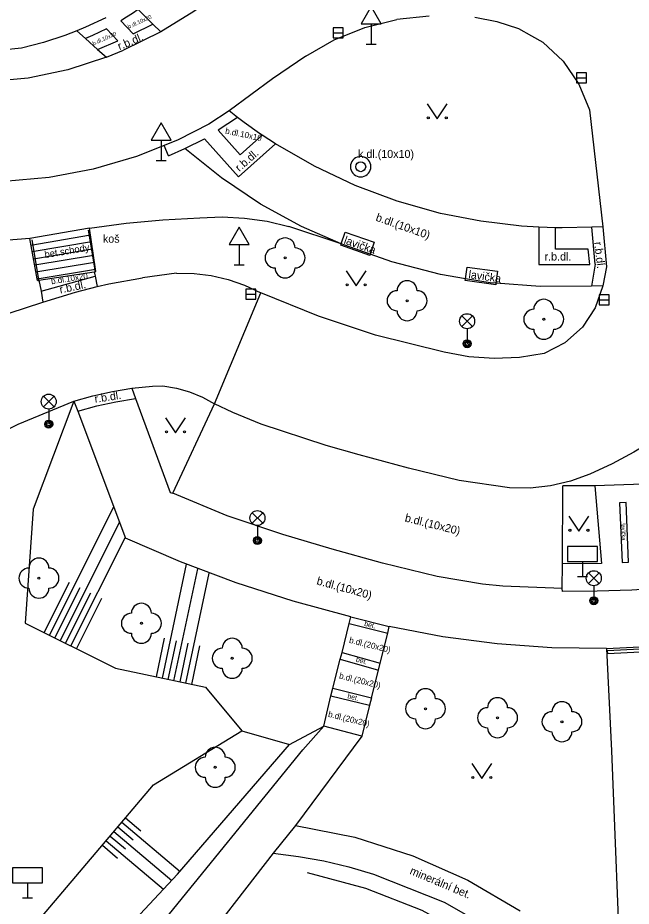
# Model space of a CAD drawing. Extents: x -600309 to -598967, y -1161267 to -1160292.
# Drawn here: x -599798.91 to -599768.25, y -1160664.5 to -1160620.07 of the extents above; entities that cross this region are included whole.
import ezdxf

# ---------------------------------------------------------------- set-up
doc = ezdxf.new("R2010")
doc.units = 0
for name, color, linetype in [('Level 10', 7, 'Continuous'), ('Level 11', 7, 'Continuous'), ('Level 14', 7, 'Continuous'), ('Level 15', 7, 'Continuous'), ('Level 20', 7, 'Continuous'), ('Level 22', 7, 'Continuous'), ('Level 24', 7, 'Continuous'), ('Level 27', 7, 'Continuous'), ('Level 28', 7, 'Continuous'), ('Level 33', 7, 'Continuous'), ('Level 34', 7, 'Continuous'), ('Level 36', 7, 'Continuous'), ('Level 40', 7, 'Continuous'), ('Level 42', 7, 'Continuous'), ('Level 53', 7, 'Continuous'), ('Level 9', 7, 'Continuous')]:
    doc.layers.add(name, color=color, linetype=linetype)

msp = doc.modelspace()

# ---------------------------------------------------------------- linework, layer by layer
at = {"layer": 'Level 10'}
for points in [[(-599784.44, -1160615.96), (-599787.36, -1160617.84), (-599790.11, -1160619.76), (-599791.76, -1160620.78), (-599793.63, -1160621.69)], [(-599794.5, -1160620.07), (-599795.52, -1160620.55), (-599795.96, -1160620.73), (-599796.56, -1160620.96), (-599797.63, -1160621.31), (-599798.72, -1160621.59)], [(-599784.51, -1160621.99), (-599783.09, -1160621.17), (-599781.57, -1160620.56), (-599779.97, -1160620.16)], [(-599778.34, -1160619.99), (-599779.97, -1160620.16)], [(-599776.07, -1160620.04), (-599774.96, -1160620.26), (-599773.88, -1160620.61)], [(-599773.88, -1160620.61), (-599773.23, -1160620.98), (-599772.67, -1160621.3), (-599771.65, -1160622.25), (-599770.86, -1160623.39), (-599770.34, -1160624.68)], [(-599798.72, -1160621.59), (-599801.69, -1160621.89), (-599808.68, -1160621.69), (-599814.39, -1160621.56)], [(-599794.48, -1160622.05), (-599793.63, -1160621.69)], [(-599784.51, -1160621.99), (-599786.17, -1160623.13), (-599788.34, -1160624.73), (-599789.36, -1160625.4)], [(-599794.48, -1160622.05), (-599796.4, -1160622.68), (-599798.39, -1160623.09), (-599800.4, -1160623.28), (-599802.43, -1160623.24)], [(-599770.34, -1160624.68), (-599769.66, -1160630.52), (-599769.48, -1160632.52), (-599769.66, -1160633.48)], [(-599789.36, -1160625.4), (-599790.9, -1160626.18)], [(-599790.9, -1160626.18), (-599791.59, -1160626.46), (-599792.98, -1160627.01), (-599795.14, -1160627.64), (-599797.34, -1160628.06), (-599799.58, -1160628.26)], [(-599797.66, -1160634.29), (-599796.02, -1160633.79), (-599794.94, -1160633.51), (-599794.36, -1160633.38), (-599792.67, -1160633.07)], [(-599790.97, -1160632.85), (-599792.67, -1160633.07)], [(-599790.97, -1160632.85), (-599790.1, -1160632.86)], [(-599790.1, -1160632.86), (-599789.24, -1160632.96)], [(-599789.24, -1160632.96), (-599788.4, -1160633.16), (-599787.58, -1160633.45)], [(-599787.58, -1160633.45), (-599786.76, -1160633.83)], [(-599769.66, -1160633.48), (-599770.05, -1160634.58), (-599770.69, -1160635.55), (-599771.56, -1160636.33), (-599772.6, -1160636.86)], [(-599777.6, -1160636.79), (-599781.03, -1160635.95), (-599783.87, -1160634.99), (-599786.76, -1160633.83)], [(-599804.11, -1160637.13), (-599802.57, -1160636.26), (-599800.98, -1160635.5), (-599799.34, -1160634.84), (-599797.66, -1160634.29)], [(-599772.6, -1160636.86), (-599773.84, -1160637.06), (-599775.1, -1160637.11), (-599776.36, -1160637.02), (-599777.6, -1160636.79)], [(-599793.21, -1160638.6), (-599792.69, -1160638.54), (-599792.17, -1160638.5), (-599791.65, -1160638.47)], [(-599791.65, -1160638.47), (-599790.97, -1160638.59), (-599790.32, -1160638.78), (-599789.68, -1160639.04), (-599789.08, -1160639.37)], [(-599796.1, -1160639.24), (-599795.15, -1160638.97), (-599794.18, -1160638.76), (-599793.21, -1160638.6)], [(-599806.53, -1160645.11), (-599804.11, -1160643.33), (-599801.55, -1160641.75), (-599798.88, -1160640.39), (-599796.1, -1160639.24)], [(-599771.7, -1160648.61), (-599774.66, -1160648.49), (-599775.69, -1160648.4), (-599777.94, -1160648.01), (-599780.68, -1160647.34), (-599783.19, -1160646.65), (-599785.66, -1160645.91), (-599788.44, -1160644.97), (-599791.16, -1160643.84), (-599789.08, -1160639.37)], [(-599762.26, -1160642.58), (-599764.7, -1160643.07), (-599767.65, -1160643.39), (-599770.07, -1160643.48), (-599771.67, -1160643.48)], [(-599771.7, -1160648.61), (-599771.68, -1160647.37), (-599771.67, -1160643.48)]]:
    msp.add_lwpolyline(points, dxfattribs=at)
at = {"layer": 'Level 11'}
for points in [[(-599793.26, -1160619.29), (-599792.89, -1160619.66), (-599792.15, -1160620.39), (-599791.76, -1160620.78)], [(-599792.89, -1160619.66), (-599793.18, -1160619.86), (-599793.47, -1160620.05), (-599793.76, -1160620.23)], [(-599793.76, -1160620.23), (-599793.14, -1160620.87)], [(-599794.47, -1160620.63), (-599794.82, -1160620.8), (-599795.18, -1160620.96), (-599795.53, -1160621.11)], [(-599794.47, -1160620.63), (-599793.91, -1160621.23)], [(-599793.14, -1160620.87), (-599792.15, -1160620.39)], [(-599795.96, -1160620.73), (-599795.53, -1160621.11), (-599794.92, -1160621.66), (-599794.48, -1160622.05)], [(-599794.92, -1160621.66), (-599793.91, -1160621.23)], [(-599787.92, -1160625.06), (-599788.89, -1160625.7)], [(-599786.03, -1160626.38), (-599786.7, -1160625.95), (-599786.82, -1160625.86), (-599787.59, -1160625.31), (-599787.92, -1160625.06), (-599788.34, -1160624.73)], [(-599787.79, -1160626.92), (-599788.89, -1160625.7)], [(-599787.79, -1160626.92), (-599786.7, -1160625.95)], [(-599791.37, -1160626.98), (-599791.59, -1160626.46)], [(-599790.56, -1160626.61), (-599789.58, -1160626.13)], [(-599786.03, -1160626.38), (-599787.87, -1160628.02), (-599789.58, -1160626.13)], [(-599779.94, -1160629.24), (-599782.05, -1160628.46), (-599784.08, -1160627.5), (-599786.03, -1160626.38)], [(-599791.37, -1160626.98), (-599790.56, -1160626.61)], [(-599782.74, -1160631.38), (-599784.72, -1160630.51), (-599786.78, -1160629.39), (-599788.73, -1160628.08), (-599790.56, -1160626.61)], [(-599781.2601, -1160627.52), (-599781.2678, -1160627.4315), (-599781.2909, -1160627.3456), (-599781.3284, -1160627.265), (-599781.3794, -1160627.1922), (-599781.4422, -1160627.1294), (-599781.515, -1160627.0784), (-599781.5956, -1160627.0409), (-599781.6815, -1160627.0178), (-599781.77, -1160627.0101), (-599781.8585, -1160627.0178), (-599781.9444, -1160627.0409), (-599782.0249, -1160627.0784), (-599782.0978, -1160627.1294), (-599782.1606, -1160627.1922), (-599782.2116, -1160627.265), (-599782.2491, -1160627.3456), (-599782.2722, -1160627.4315), (-599782.2799, -1160627.52), (-599782.2722, -1160627.6085), (-599782.2491, -1160627.6944), (-599782.2116, -1160627.7749), (-599782.1606, -1160627.8478), (-599782.0978, -1160627.9106), (-599782.0249, -1160627.9616), (-599781.9444, -1160627.9991), (-599781.8585, -1160628.0222), (-599781.77, -1160628.0299), (-599781.6815, -1160628.0222), (-599781.5956, -1160627.9991), (-599781.515, -1160627.9616), (-599781.4422, -1160627.9106), (-599781.3794, -1160627.8478), (-599781.3284, -1160627.7749), (-599781.2909, -1160627.6944), (-599781.2678, -1160627.6085), (-599781.2601, -1160627.52)], [(-599777.78, -1160629.86), (-599779.94, -1160629.24)], [(-599789.81, -1160630.07), (-599788.69, -1160630.03), (-599787.57, -1160630.09), (-599786.45, -1160630.25), (-599785.36, -1160630.51)], [(-599773.74, -1160630.49), (-599775.77, -1160630.25), (-599777.78, -1160629.86)], [(-599795.32, -1160630.59), (-599793.49, -1160630.34), (-599791.65, -1160630.17), (-599789.81, -1160630.07)], [(-599795.32, -1160630.59), (-599798.31, -1160631.11)], [(-599795, -1160632.76), (-599795.02, -1160632.64), (-599795.32, -1160630.59)], [(-599782.74, -1160631.38), (-599785.36, -1160630.51)], [(-599769.66, -1160630.52), (-599770.22, -1160630.54), (-599771.7, -1160630.58), (-599772.04, -1160630.57), (-599772.86, -1160630.55), (-599773.74, -1160630.49)], [(-599772.86, -1160630.55), (-599772.86, -1160632.41)], [(-599772.04, -1160631.64), (-599772.04, -1160630.57)], [(-599770.05, -1160632.4), (-599770.22, -1160630.54)], [(-599798.31, -1160631.11), (-599799.79, -1160631.22), (-599801.28, -1160631.25), (-599802.77, -1160631.21), (-599804.25, -1160631.09)], [(-599797.92, -1160633.21), (-599797.94, -1160633.12), (-599798.31, -1160631.11)], [(-599798.25, -1160631.45), (-599795.27, -1160630.93)], [(-599795.22, -1160631.27), (-599798.19, -1160631.78)], [(-599798.13, -1160632.12), (-599795.17, -1160631.62)], [(-599782.57, -1160631.44), (-599782.74, -1160631.38)], [(-599781.3, -1160631.89), (-599782.57, -1160631.44)], [(-599770.4, -1160631.64), (-599772.04, -1160631.64)], [(-599770.32, -1160632.41), (-599770.4, -1160631.64)], [(-599795.12, -1160631.96), (-599798.06, -1160632.45)], [(-599776.53, -1160633.12), (-599777.78, -1160632.91), (-599780.21, -1160632.28), (-599781.3, -1160631.89)], [(-599798, -1160632.78), (-599795.07, -1160632.3)], [(-599797.94, -1160633.12), (-599795.02, -1160632.64)], [(-599772.86, -1160632.41), (-599770.32, -1160632.41)], [(-599770.05, -1160632.4), (-599770.24, -1160633.49)], [(-599797.85, -1160633.2), (-599795.09, -1160632.77)], [(-599797.74, -1160633.74), (-599795.04, -1160632.99)], [(-599795.09, -1160632.77), (-599795, -1160632.76)], [(-599795.09, -1160632.77), (-599795.04, -1160632.99), (-599794.94, -1160633.51)], [(-599775.01, -1160633.34), (-599775.3, -1160633.32), (-599776.53, -1160633.12)], [(-599797.92, -1160633.21), (-599797.85, -1160633.2)], [(-599797.85, -1160633.2), (-599797.74, -1160633.74), (-599797.66, -1160634.29)], [(-599772.8, -1160633.51), (-599775.01, -1160633.34)], [(-599769.66, -1160633.48), (-599770.24, -1160633.49), (-599772.8, -1160633.51)], [(-599789.08, -1160639.37), (-599786.76, -1160633.83)], [(-599793.21, -1160638.6), (-599793.02, -1160639.11), (-599791.29, -1160643.81)], [(-599796.1, -1160639.24), (-599795.91, -1160639.74), (-599793.52, -1160646.09)], [(-599795.91, -1160639.74), (-599794.96, -1160639.48), (-599794, -1160639.27), (-599793.02, -1160639.11)], [(-599774.33, -1160643.58), (-599776.85, -1160643.21), (-599779.38, -1160642.6), (-599781.84, -1160641.92), (-599783.5, -1160641.46), (-599786.74, -1160640.39), (-599788.16, -1160639.81), (-599789.08, -1160639.37)], [(-599767.06, -1160641.16), (-599768.12, -1160641.79), (-599769.2, -1160642.37), (-599770.32, -1160642.89)], [(-599770.32, -1160642.89), (-599771.29, -1160643.24), (-599772.28, -1160643.47), (-599773.3, -1160643.59), (-599774.33, -1160643.58)], [(-599770.07, -1160643.48), (-599769.73, -1160647.36), (-599771.68, -1160647.37)], [(-599791.29, -1160643.81), (-599791.16, -1160643.84)], [(-599782.26, -1160650.02), (-599785.14, -1160649.24), (-599787.99, -1160648.33), (-599790.78, -1160647.28), (-599793.52, -1160646.09)], [(-599771.69, -1160648.76), (-599771.7, -1160648.61)], [(-599765.36, -1160648.45), (-599766.49, -1160648.57), (-599768.22, -1160648.69), (-599769.95, -1160648.75), (-599771.69, -1160648.76)], [(-599782.34, -1160650.36), (-599782.26, -1160650.02)], [(-599782.26, -1160650.02), (-599780.34, -1160650.51)], [(-599782.7, -1160651.81), (-599782.34, -1160650.36)], [(-599782.34, -1160650.36), (-599780.42, -1160650.85)], [(-599782.34, -1160650.36), (-599780.42, -1160650.85)], [(-599780.79, -1160652.34), (-599780.42, -1160650.85)], [(-599780.42, -1160650.85), (-599780.34, -1160650.51)], [(-599769.49, -1160651.61), (-599772.22, -1160651.58), (-599774.95, -1160651.38), (-599777.66, -1160651.03), (-599780.34, -1160650.51)], [(-599769.49, -1160651.61), (-599766.48, -1160651.46)], [(-599769.49, -1160651.61), (-599769.24, -1160656.73), (-599768.75, -1160668.89), (-599768.65, -1160671.24)], [(-599783.17, -1160653.6), (-599782.79, -1160652.15)], [(-599782.79, -1160652.15), (-599782.7, -1160651.81)], [(-599782.79, -1160652.15), (-599780.88, -1160652.69)], [(-599782.79, -1160652.15), (-599780.88, -1160652.69)], [(-599782.7, -1160651.81), (-599780.79, -1160652.34)], [(-599782.7, -1160651.81), (-599780.79, -1160652.34)], [(-599780.88, -1160652.69), (-599780.79, -1160652.34)], [(-599781.23, -1160654.07), (-599780.88, -1160652.69)], [(-599783.62, -1160655.49), (-599783.26, -1160653.97)], [(-599783.26, -1160653.97), (-599783.17, -1160653.6)], [(-599783.26, -1160653.97), (-599781.33, -1160654.44)], [(-599783.26, -1160653.97), (-599781.33, -1160654.44)], [(-599783.17, -1160653.6), (-599781.23, -1160654.07)], [(-599783.17, -1160653.6), (-599781.23, -1160654.07)], [(-599781.33, -1160654.44), (-599781.72, -1160655.99)], [(-599781.23, -1160654.07), (-599781.33, -1160654.44)], [(-599797.31, -1160672.52), (-599791.97, -1160665.67), (-599784.66, -1160656.67), (-599783.62, -1160655.49)], [(-599781.72, -1160655.99), (-599783.62, -1160655.49)], [(-599781.72, -1160655.99), (-599785.02, -1160660.46), (-599786.15, -1160661.85), (-599790.33, -1160667.24), (-599798.33, -1160676.81), (-599799.35, -1160677.77), (-599802.92, -1160681.85), (-599804.76, -1160683.39)], [(-599785.02, -1160660.46), (-599782.06, -1160661.05), (-599779.17, -1160661.97), (-599776.41, -1160663.2), (-599773.8, -1160664.72)], [(-599786.15, -1160661.85), (-599784.88, -1160662.01), (-599783.61, -1160662.23), (-599782.36, -1160662.53), (-599781.13, -1160662.89)], [(-599781.13, -1160662.89), (-599777.6, -1160664.29), (-599774.3, -1160666.18), (-599771.29, -1160668.51), (-599768.65, -1160671.24)]]:
    msp.add_lwpolyline(points, dxfattribs=at)
at = {"layer": 'Level 14'}
for points in [[(-599796.1, -1160639.24), (-599798.14, -1160644.64), (-599798.53, -1160650.34), (-599794.02, -1160652.6), (-599789.53, -1160653.55), (-599787.71, -1160655.72)], [(-599811.25, -1160687.12), (-599808.75, -1160676.96), (-599799.33, -1160666.94), (-599792.12, -1160658.42), (-599787.71, -1160655.72), (-599785.33, -1160656.41), (-599783.62, -1160655.49)], [(-599807.49, -1160680.78), (-599805.48, -1160677.88), (-599796.75, -1160669.14), (-599790.92, -1160662.9), (-599785.33, -1160656.41)]]:
    msp.add_lwpolyline(points, dxfattribs=at)
at = {"layer": 'Level 15'}
for points in [[(-599797.32, -1160650.95), (-599794.11, -1160644.53)], [(-599796.78, -1160651.21), (-599793.82, -1160645.3)], [(-599796.25, -1160651.48), (-599793.54, -1160646.08)], [(-599791.68, -1160653.09), (-599790.48, -1160647.4)], [(-599791.1, -1160653.22), (-599789.91, -1160647.62)], [(-599790.51, -1160653.34), (-599789.34, -1160647.84)], [(-599797.59, -1160650.81), (-599796.32, -1160648.29)], [(-599797.05, -1160651.08), (-599795.79, -1160648.56)], [(-599796.52, -1160651.35), (-599795.25, -1160648.83)], [(-599795.98, -1160651.62), (-599794.71, -1160649.09)], [(-599791.98, -1160653.03), (-599791.57, -1160651.1)], [(-599791.39, -1160653.16), (-599790.98, -1160651.22)], [(-599790.8, -1160653.28), (-599790.39, -1160651.35)], [(-599790.21, -1160653.41), (-599789.81, -1160651.47)], [(-599793.52, -1160660.07), (-599792.75, -1160660.72)], [(-599793.9, -1160660.53), (-599793.14, -1160661.17)], [(-599793.71, -1160660.3), (-599790.8, -1160662.76)], [(-599794.29, -1160660.99), (-599793.53, -1160661.63)], [(-599794.1, -1160660.76), (-599791.21, -1160663.21)], [(-599794.68, -1160661.44), (-599793.92, -1160662.09)], [(-599794.49, -1160661.22), (-599791.62, -1160663.64)]]:
    msp.add_lwpolyline(points, dxfattribs=at)
at = {"layer": 'Level 20'}
msp.add_lwpolyline([(-599784.45, -1160662.81), (-599781.53, -1160663.59), (-599778.72, -1160664.7), (-599776.06, -1160666.14), (-599773.59, -1160667.88)], dxfattribs=at)
at = {"layer": 'Level 22'}
for centre in [(-599785.55, -1160632.08), (-599779.45, -1160634.22), (-599772.62, -1160635.15), (-599797.85, -1160648.09), (-599792.73, -1160650.35), (-599788.19, -1160652.1), (-599778.53, -1160654.62), (-599774.93, -1160655.07), (-599771.71, -1160655.27), (-599789.04, -1160657.55)]:
    msp.add_circle(centre, 0.05, dxfattribs=at)
for centre, start, end in [((-599785.55, -1160631.58), 0, 180), ((-599786.05, -1160632.08), 90, 270), ((-599785.05, -1160632.08), 270, 90), ((-599785.55, -1160632.58), 180, 0), ((-599779.45, -1160633.72), 0, 180), ((-599779.95, -1160634.22), 90, 270), ((-599778.95, -1160634.22), 270, 90), ((-599772.62, -1160634.65), 0, 180), ((-599779.45, -1160634.72), 180, 0), ((-599773.12, -1160635.15), 90, 270), ((-599772.12, -1160635.15), 270, 90), ((-599772.62, -1160635.65), 180, 0), ((-599797.85, -1160647.59), 0, 180), ((-599798.35, -1160648.09), 90, 270), ((-599797.35, -1160648.09), 270, 90), ((-599797.85, -1160648.59), 180, 0), ((-599792.73, -1160649.85), 0, 180), ((-599793.23, -1160650.35), 90, 270), ((-599792.23, -1160650.35), 270, 90), ((-599792.73, -1160650.85), 180, 0), ((-599788.19, -1160651.6), 0, 180), ((-599788.69, -1160652.1), 90, 270), ((-599787.69, -1160652.1), 270, 90), ((-599788.19, -1160652.6), 180, 0), ((-599778.53, -1160654.12), 0, 180), ((-599779.03, -1160654.62), 90, 270), ((-599778.03, -1160654.62), 270, 90), ((-599774.93, -1160654.57), 0, 180), ((-599771.71, -1160654.77), 0, 180), ((-599775.43, -1160655.07), 90, 270), ((-599774.43, -1160655.07), 270, 90), ((-599772.21, -1160655.27), 90, 270), ((-599771.21, -1160655.27), 270, 90), ((-599778.53, -1160655.12), 180, 0), ((-599774.93, -1160655.57), 180, 0), ((-599771.71, -1160655.77), 180, 0), ((-599789.04, -1160657.05), 0, 180), ((-599789.54, -1160657.55), 90, 270), ((-599788.54, -1160657.55), 270, 90), ((-599789.04, -1160658.05), 180, 0)]:
    msp.add_arc(centre, 0.5, start, end, dxfattribs=at)
at = {"layer": 'Level 24'}
for points in [[(-599766.48, -1160651.58), (-599769.45, -1160651.73)], [(-599769.45, -1160651.73), (-599769.44, -1160651.86)], [(-599769.44, -1160651.86), (-599766.47, -1160651.71)]]:
    msp.add_lwpolyline(points, dxfattribs=at)
at = {"layer": 'Level 27'}
for p, q in [((-599783.14, -1160620.82), (-599782.64, -1160620.82)), ((-599770.99, -1160623.07), (-599770.49, -1160623.07)), ((-599787.51, -1160633.89), (-599787.01, -1160633.89)), ((-599769.85, -1160634.18), (-599769.35, -1160634.18))]:
    msp.add_line(p, q, dxfattribs=at)
for points in [[(-599783.14, -1160621.07), (-599782.64, -1160621.07), (-599782.64, -1160620.57), (-599783.14, -1160620.57)], [(-599770.99, -1160623.32), (-599770.49, -1160623.32), (-599770.49, -1160622.82), (-599770.99, -1160622.82)], [(-599787.51, -1160634.14), (-599787.01, -1160634.14), (-599787.01, -1160633.64), (-599787.51, -1160633.64)], [(-599769.85, -1160634.43), (-599769.35, -1160634.43), (-599769.35, -1160633.93), (-599769.85, -1160633.93)]]:
    msp.add_lwpolyline(points, close=True, dxfattribs=at)
at = {"layer": 'Level 28'}
msp.add_circle((-599781.77, -1160627.52), 0.25, dxfattribs=at)
at = {"layer": 'Level 33'}
for p, q in [((-599776.715, -1160635.51), (-599776.185, -1160634.98)), ((-599776.715, -1160634.98), (-599776.185, -1160635.51)), ((-599776.45, -1160635.62), (-599776.45, -1160636.37)), ((-599797.625, -1160639.53), (-599797.095, -1160639)), ((-599797.625, -1160639), (-599797.095, -1160639.53)), ((-599797.36, -1160639.64), (-599797.36, -1160640.39)), ((-599787.195, -1160645.35), (-599786.665, -1160644.82)), ((-599787.195, -1160644.82), (-599786.665, -1160645.35)), ((-599786.93, -1160645.46), (-599786.93, -1160646.21)), ((-599770.385, -1160648.36), (-599769.855, -1160647.83)), ((-599770.385, -1160647.83), (-599769.855, -1160648.36)), ((-599770.12, -1160648.47), (-599770.12, -1160649.22))]:
    msp.add_line(p, q, dxfattribs=at)
for centre, radius in [((-599776.45, -1160635.245), 0.375), ((-599776.45, -1160636.37), 0.2), ((-599776.45, -1160636.37), 0.1445), ((-599776.45, -1160636.37), 0.0876), ((-599797.36, -1160639.265), 0.375), ((-599797.36, -1160640.39), 0.2), ((-599797.36, -1160640.39), 0.1445), ((-599797.36, -1160640.39), 0.0876), ((-599786.93, -1160645.085), 0.375), ((-599786.93, -1160646.21), 0.2), ((-599786.93, -1160646.21), 0.1445), ((-599786.93, -1160646.21), 0.0876), ((-599770.12, -1160648.095), 0.375), ((-599770.12, -1160649.22), 0.2), ((-599770.12, -1160649.22), 0.1445), ((-599770.12, -1160649.22), 0.0876)]:
    msp.add_circle(centre, radius, dxfattribs=at)
at = {"layer": 'Level 34'}
for p, q in [((-599781.25, -1160620.382), (-599781.25, -1160621.4)), ((-599781.5, -1160621.4), (-599781, -1160621.4)), ((-599791.74, -1160626.192), (-599791.74, -1160627.21)), ((-599791.99, -1160627.21), (-599791.49, -1160627.21)), ((-599787.84, -1160631.402), (-599787.84, -1160632.42)), ((-599788.09, -1160632.42), (-599787.59, -1160632.42)), ((-599770.68, -1160647.26), (-599770.68, -1160648.01)), ((-599770.93, -1160648.01), (-599770.43, -1160648.01)), ((-599798.42, -1160663.33), (-599798.42, -1160664.08)), ((-599798.67, -1160664.08), (-599798.17, -1160664.08))]:
    msp.add_line(p, q, dxfattribs=at)
for points in [[(-599781.75, -1160620.382), (-599780.75, -1160620.382), (-599781.25, -1160619.516)], [(-599792.24, -1160626.192), (-599791.24, -1160626.192), (-599791.74, -1160625.326)], [(-599788.34, -1160631.402), (-599787.34, -1160631.402), (-599787.84, -1160630.536)], [(-599771.43, -1160647.26), (-599769.93, -1160647.26), (-599769.93, -1160646.51), (-599771.43, -1160646.51)], [(-599799.17, -1160663.33), (-599797.67, -1160663.33), (-599797.67, -1160662.58), (-599799.17, -1160662.58)]]:
    msp.add_lwpolyline(points, close=True, dxfattribs=at)
at = {"layer": 'Level 36'}
for points in [[(-599778.44, -1160624.38), (-599777.94, -1160625.13), (-599777.44, -1160624.38)], [(-599782.49, -1160632.72), (-599781.99, -1160633.47), (-599781.49, -1160632.72)], [(-599791.52, -1160640.08), (-599791.02, -1160640.83), (-599790.52, -1160640.08)], [(-599771.36, -1160645), (-599770.86, -1160645.75), (-599770.36, -1160645)], [(-599776.22, -1160657.36), (-599775.72, -1160658.11), (-599775.22, -1160657.36)]]:
    msp.add_lwpolyline(points, dxfattribs=at)
for centre in [(-599778.3902, -1160625.0798), (-599777.4908, -1160625.0798), (-599782.4402, -1160633.4198), (-599781.5408, -1160633.4198), (-599791.4702, -1160640.7798), (-599790.5708, -1160640.7798), (-599771.3102, -1160645.6998), (-599770.4108, -1160645.6998), (-599776.1702, -1160658.0598), (-599775.2708, -1160658.0598)]:
    msp.add_circle(centre, 0.05, dxfattribs=at)
at = {"layer": 'Level 53'}
for points in [[(-599782.74, -1160631.38), (-599782.54, -1160630.79)], [(-599782.54, -1160630.79), (-599781.09, -1160631.3)], [(-599781.09, -1160631.3), (-599781.3, -1160631.89)], [(-599782.77, -1160631.45), (-599782.74, -1160631.38)], [(-599781.32, -1160631.96), (-599782.77, -1160631.45)], [(-599781.3, -1160631.89), (-599781.32, -1160631.96)], [(-599776.53, -1160633.12), (-599776.45, -1160632.54)], [(-599776.45, -1160632.54), (-599774.93, -1160632.75)], [(-599776.54, -1160633.21), (-599776.53, -1160633.12)], [(-599774.93, -1160632.75), (-599775.01, -1160633.34)], [(-599775.02, -1160633.42), (-599776.54, -1160633.21)], [(-599775.01, -1160633.34), (-599775.02, -1160633.42)], [(-599768.5, -1160644.31), (-599768.83, -1160644.32)], [(-599768.83, -1160644.32), (-599768.71, -1160647.31)], [(-599768.38, -1160647.3), (-599768.5, -1160644.31)], [(-599768.71, -1160647.31), (-599768.38, -1160647.3)]]:
    msp.add_lwpolyline(points, dxfattribs=at)
at = {"layer": 'Level 9'}
for points in [[(-599795.03, -1160632.8), (-599795.38, -1160630.7)], [(-599798.21, -1160631.17), (-599797.86, -1160633.26)]]:
    msp.add_lwpolyline(points, dxfattribs=at)

# ---------------------------------------------------------------- texts
at = {"layer": 'Level 40'}
for s, height, rotation, p in [('b.dl.10x20', 0.2, 24.17, (-599793.36, -1160620.62)), ('b.dl.10x20', 0.2, 24.17, (-599795.12, -1160621.46)), ('r.b.dl.', 0.4, 22.95, (-599793.82, -1160621.7)), ('b.dl.10x10', 0.3, 348, (-599788.56, -1160625.86)), ('r.b.dl.', 0.4, 41.71, (-599787.83, -1160627.79)), ('b.dl.(10x10)', 0.4, 340.61, (-599781.05, -1160630.21)), ('r.b.dl.', 0.4, 276.64, (-599770.1, -1160631.3)), ('b.dl.10x20', 0.3, 8.86, (-599797.22, -1160633.4)), ('r.b.dl.', 0.4, 12, (-599796.78, -1160633.86)), ('r.b.dl.', 0.4, 8.86, (-599795.04, -1160639.33)), ('b.dl.(10x20)', 0.4, 346, (-599779.59, -1160645.25)), ('b.dl.(10x20)', 0.4, 344.72, (-599784, -1160648.4)), ('bet.', 0.25, 345.68, (-599781.61, -1160650.47)), ('b.dl.(20x20)', 0.3, 346, (-599782.37, -1160651.32)), ('bet.', 0.25, 344.49, (-599782.03, -1160652.26)), ('b.dl.(20x20)', 0.3, 346, (-599782.87, -1160653.1)), ('bet.', 0.25, 346.38, (-599782.45, -1160654.09)), ('b.dl.(20x20)', 0.3, 346, (-599783.42, -1160655.02)), ('minerální bet.', 0.4, 337.19, (-599779.35, -1160662.87))]:
    msp.add_text(s, height=height, rotation=rotation, dxfattribs=at).set_placement(p)
for s, p in [('k.dl.(10x10)', (-599781.9, -1160627.08)), ('r.b.dl.', (-599772.58, -1160632.21))]:
    msp.add_text(s, height=0.4, dxfattribs=at).set_placement(p)
at = {"layer": 'Level 42'}
msp.add_text('koš', height=0.4, dxfattribs=at).set_placement((-599794.65, -1160631.32))
for s, height, rotation, p in [('lavička', 0.4, 340.62, (-599782.64, -1160631.35)), ('bet.schody', 0.35, 9.51, (-599797.54, -1160632.09)), ('lavička', 0.4, 352.13, (-599776.4, -1160633.09)), ('lavička', 0.2, 272.3, (-599768.74, -1160645.36))]:
    msp.add_text(s, height=height, rotation=rotation, dxfattribs=at).set_placement(p)

doc.saveas('drawing.dxf')
